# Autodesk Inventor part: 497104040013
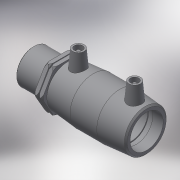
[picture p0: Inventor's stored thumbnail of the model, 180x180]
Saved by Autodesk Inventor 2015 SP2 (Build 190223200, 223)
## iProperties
Created: 2017-06
Part Number: 497104040013
Material: Generic
Description: PLASSON PE MALE TRANSITION COUPLER 40-1.1/4"
Document SubType Name: Modeling
Designer: KIM
Mass: 55.0731 g
Surface Area: 148.067 cm^2
Volume: 55.0731 cm^3
Density: 1 g/cm^3
Appearance: Default
Author: KIM
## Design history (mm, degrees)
derived "497104.ipt"
feature "Solid1::497104.ipt"
tag "TaggingFeature1"
body "Solid1"
other parameters: "d0" = 97, "d2" = 56, "d3" = 47, "d4" = 32.33333, "d5" = 50.4, "d6" = 38, "d8" = 168 deg, "d10" = 18.8, "d11" = 6.26667, "d29" = 46, "d30" = 14, "d31" = 33.95, "d34" = 5 deg, "d41" = 4, "d42" = 14, "d43" = 0, "d48" = 3, "d49" = 0, "d58" = 41.91, "d59" = 33.528, "d60" = 36, "d61" = 58.674, "d62" = 0.8382, "d65" = 1.68, "d70" = 0.1, "d73" = 18.8, "d75" = 0, "d76" = 1, "d77" = 4.5, "d78" = 58.674, "L_" = 137, "L_2" = 47, "D_1" = 56, "A_" = 46, "d_2" = 12, "R_" = 41.91
